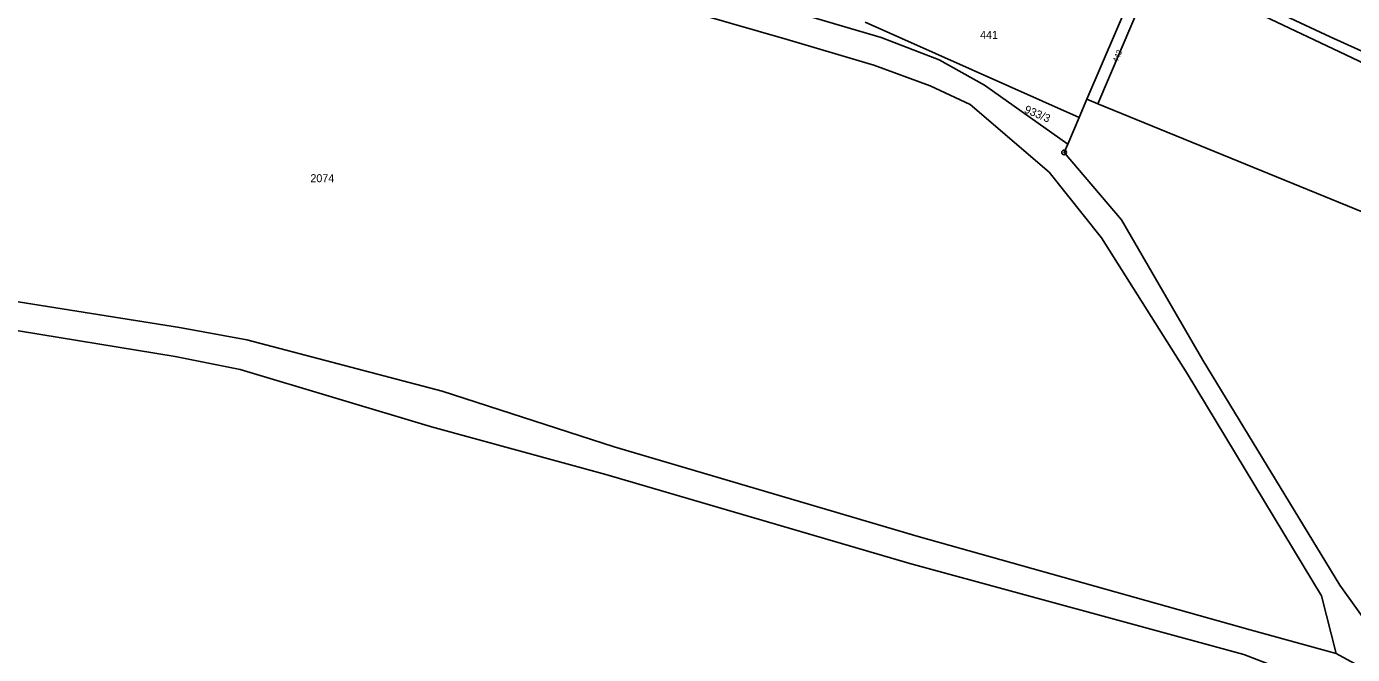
# Model space of a CAD drawing. Extents: x -504988 to -494607, y -1123820 to -1114018.
# Drawn here: x -500371.7 to -500090, y -1121310 to -1121176.7 of the extents above; entities that cross this region are included whole.
import ezdxf

# ---------------------------------------------------------------- set-up
doc = ezdxf.new("R2010")
doc.units = 0
for name, color, linetype in [('Hranice parcel', 7, 'Continuous'), ('Parcelní čísla', 7, 'Continuous'), ('Vnitřní kresba', 7, 'Continuous'), ('Značky bodu BP', 7, 'Continuous')]:
    doc.layers.add(name, color=color, linetype=linetype)

msp = doc.modelspace()

# ---------------------------------------------------------------- linework, layer by layer
at = {"layer": 'Hranice parcel'}
for p, q in [((-500133.8, -1121162.56), (-500146.46, -1121192.11)), ((-500144.15, -1121193.06), (-500131.54, -1121163.63)), ((-500193.58, -1121175.73), (-500148.1, -1121195.96)), ((-500148.1, -1121195.96), (-500146.46, -1121192.11)), ((-500146.46, -1121192.11), (-500144.15, -1121193.06)), ((-500148.1, -1121195.96), (-500150.54, -1121201.64)), ((-500093.53, -1121309.79), (-500074.14, -1121320.39))]:
    msp.add_line(p, q, dxfattribs=at)
for points in [[(-500093.53, -1121309.79), (-500096.64, -1121297.58), (-500125.14, -1121250.31), (-500143.37, -1121221.49), (-500154.49, -1121207.58), (-500171.25, -1121193.24), (-500179.79, -1121189.25), (-500191.69, -1121184.83), (-500210.15, -1121179.42), (-500240.92, -1121170.5), (-500265.19, -1121164.1), (-500289.32, -1121158.74), (-500305.17, -1121156.16), (-500321.82, -1121158.18), (-500359.14, -1121160.88), (-500369.12, -1121161.84), (-500376.67, -1121161), (-500384.33, -1121158.44), (-500393.5, -1121153.73), (-500419.45, -1121136.05), (-500446.85, -1121123.24)], [(-500131.54, -1121163.63), (-500071.42, -1121192.12), (-500041.43, -1121205.99), (-500018.61, -1121215)], [(-500150.54, -1121201.64), (-500168.18, -1121189.1), (-500177.87, -1121183.75), (-500190.18, -1121178.97), (-500209.2, -1121173.36)], [(-500099.19, -1121315.37), (-500113.09, -1121309.98), (-500184.11, -1121290.7), (-500248.64, -1121271.81), (-500285.69, -1121261.64), (-500326.32, -1121249.51), (-500340.18, -1121246.71), (-500467.78, -1121225.87), (-500520.34, -1121217.8), (-500582.53, -1121209), (-500625.06, -1121202.79), (-500658.2, -1121198.42), (-500690.57, -1121193.22)], [(-500144.15, -1121193.06), (-500082.97, -1121218.02), (-500022.96, -1121242.74)], [(-500074.14, -1121320.39), (-500082.16, -1121310.01), (-500092.71, -1121295.25), (-500121.86, -1121247.48), (-500139.08, -1121217.71), (-500151.3, -1121203.4), (-500150.54, -1121201.64)], [(-500465.32, -1121220.56), (-500339.23, -1121240.59), (-500324.95, -1121243.16), (-500283.43, -1121254.1), (-500246.86, -1121265.89), (-500182.29, -1121284.98), (-500111.77, -1121304.75), (-500093.53, -1121309.79)]]:
    msp.add_lwpolyline(points, dxfattribs=at)
at = {"layer": 'Vnitřní kresba'}
for p, q in [((-500094.76, -1121178.83), (-500133.27, -1121160.81)), ((-500055.9, -1121196.62), (-500094.76, -1121178.83))]:
    msp.add_line(p, q, dxfattribs=at)
at = {"layer": 'Značky bodu BP'}
for radius in [0.5, 0.0303]:
    msp.add_circle((-500151.3, -1121203.4), radius, dxfattribs=at)

# ---------------------------------------------------------------- texts
at = {"layer": 'Parcelní čísla'}
for s, p in [('441', (-500169.14, -1121179.27)), ('2074', (-500311.43, -1121209.71))]:
    msp.add_text(s, height=1.7, dxfattribs=at).set_placement(p)
for s, height, rotation, p in [('442', 1.2, 67, (-500139.96, -1121184.39)), ('933/3', 1.7, 337, (-500159.91, -1121194.86))]:
    msp.add_text(s, height=height, rotation=rotation, dxfattribs=at).set_placement(p)

doc.saveas('drawing.dxf')
